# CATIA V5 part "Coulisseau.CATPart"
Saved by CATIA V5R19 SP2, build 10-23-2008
Part number: Coulisseau
Bounding box of the stored display mesh (mm): x -10 to 10, y -9.997 to 32, z 125 to 175
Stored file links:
  D:\France\IFMA\IAO\Projet\Coulisseau.CATPart
  D:\France\IFMA\IAO\Projet\pruangdaja_CAO.CATProduct
  D:\France\IFMA\IAO\Projet\SqueletteCoulisseau.CATPart
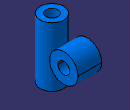
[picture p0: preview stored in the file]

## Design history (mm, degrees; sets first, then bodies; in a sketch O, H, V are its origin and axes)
Body1 (main body)
Body2
  Solid1: linked copy from another document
